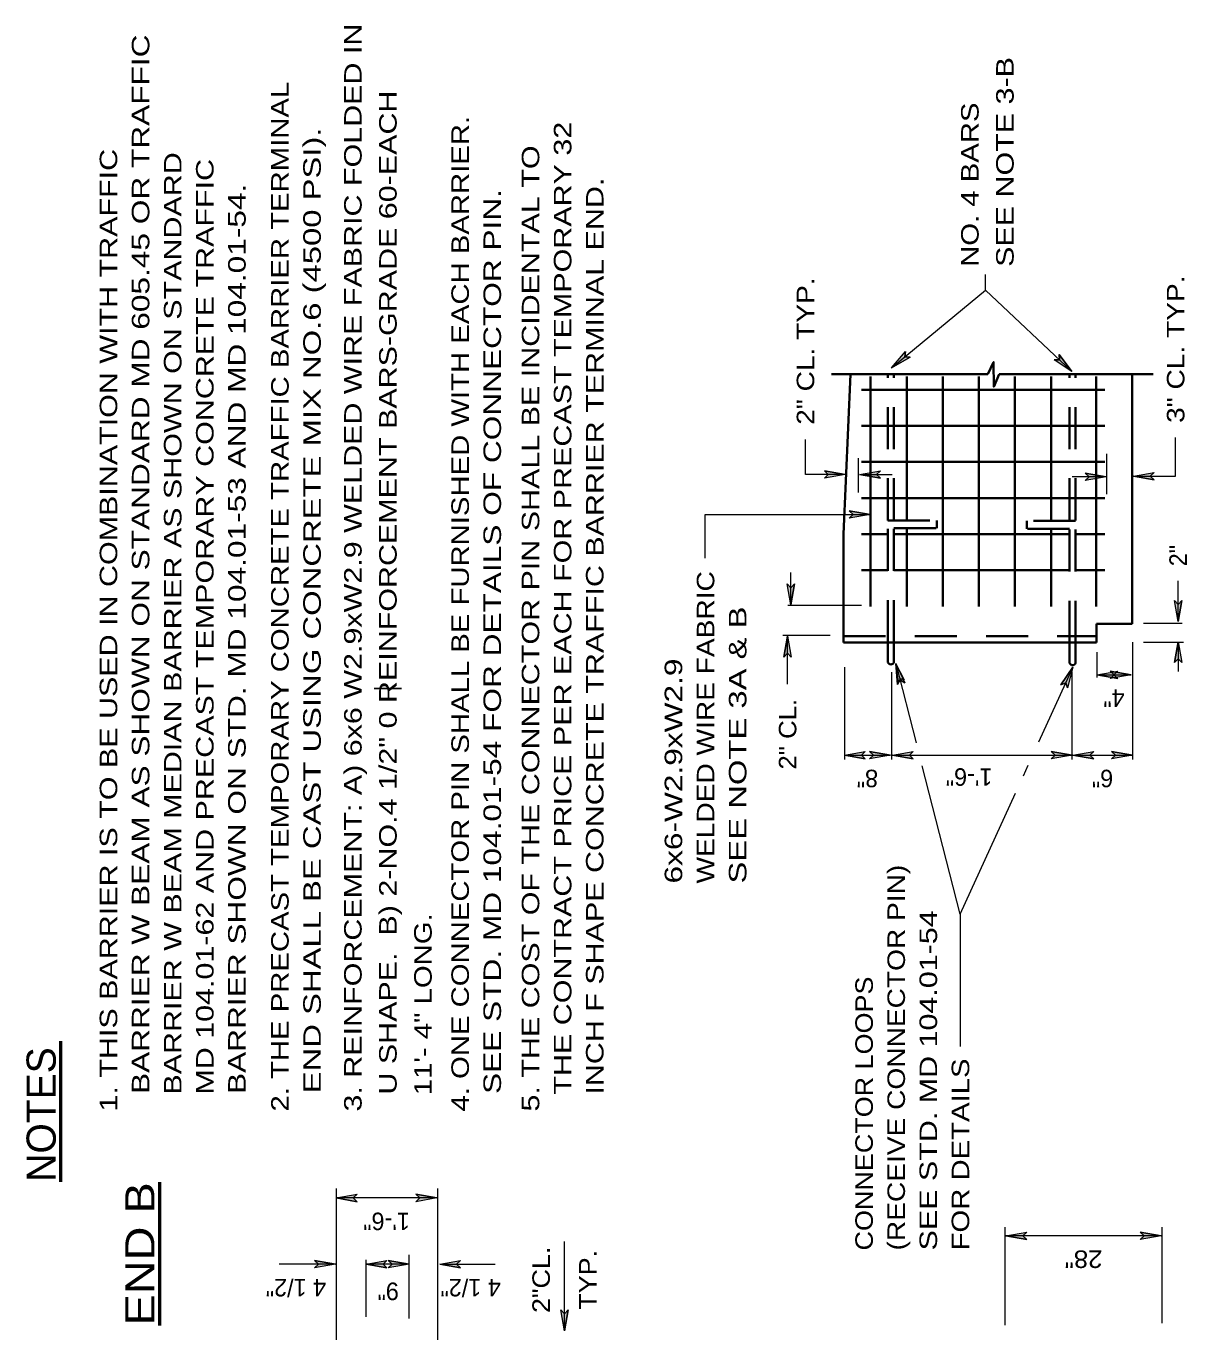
# Model space of a CAD drawing. Extents: x 12.6 to 19.4, y 6.1 to 16.3.
# Drawn here: x 12.609 to 16.585, y 11.844 to 16.317 of the extents above; entities that cross this region are included whole.
import ezdxf
from ezdxf.enums import TextEntityAlignment as Align

# ---------------------------------------------------------------- set-up
doc = ezdxf.new("R2010")
doc.units = 0
doc.header["$LTSCALE"] = 0.024
doc.linetypes.add('LONG_DASHED', pattern=[7.5, 6, -1.5])
for name, color, linetype, lineweight in [('1', 7, 'Continuous', 35), ('10', 7, 'Continuous', 13), ('12', 7, 'Continuous', 53), ('13', 7, 'Continuous', 53)]:
    doc.layers.add(name, color=color, linetype=linetype, lineweight=lineweight)

msp = doc.modelspace()

# ---------------------------------------------------------------- hatches: boundary and pattern name
at = {"layer": '10'}
for points in [[(15.6367, 15.1824), (15.5735, 15.1466), (15.6206, 15.2018), (15.6182, 15.1835)], [(16.1475, 15.1916), (16.1909, 15.1334), (16.1302, 15.1733), (16.1487, 15.1732)], [(15.3432, 14.7935), (15.4147, 14.7809), (15.3432, 14.7683), (15.3567, 14.7809)], [(15.5351, 14.7683), (15.4636, 14.7809), (15.5351, 14.7935), (15.5216, 14.7809)], [(16.2369, 14.7857), (16.3084, 14.7731), (16.2369, 14.7605), (16.2504, 14.7731)], [(16.4731, 14.7626), (16.4016, 14.7752), (16.4731, 14.7878), (16.4596, 14.7752)], [(15.4286, 14.6562), (15.5001, 14.6436), (15.4286, 14.631), (15.4421, 14.6436)], [(15.2411, 14.4059), (15.2285, 14.3344), (15.2159, 14.4059), (15.2285, 14.3924)], [(16.5675, 14.3487), (16.5549, 14.2772), (16.5423, 14.3487), (16.5549, 14.3352)], [(15.2046, 14.1552), (15.2172, 14.2267), (15.2298, 14.1552), (15.2172, 14.1687)], [(16.5423, 14.1362), (16.5549, 14.2077), (16.5675, 14.1362), (16.5549, 14.1497)], [(15.5938, 14.0612), (15.5883, 14.1336), (15.6182, 14.0675), (15.6027, 14.0774)], [(16.1528, 14.0604), (16.1939, 14.1202), (16.1757, 14.0499), (16.1698, 14.0674)], [(16.3484, 14.0821), (16.2769, 14.0947), (16.3484, 14.1073), (16.3349, 14.0947)], [(16.3224, 14.1073), (16.3939, 14.0947), (16.3224, 14.0821), (16.3359, 14.0947)], [(15.4833, 13.8069), (15.4118, 13.8195), (15.4833, 13.8321), (15.4698, 13.8195)], [(15.4979, 13.8321), (15.5694, 13.8195), (15.4979, 13.8069), (15.5114, 13.8195)], [(15.6478, 13.8069), (15.5763, 13.8195), (15.6478, 13.8321), (15.6343, 13.8195)], [(16.1204, 13.8321), (16.1919, 13.8195), (16.1204, 13.8069), (16.1339, 13.8195)], [(16.2656, 13.8069), (16.1941, 13.8195), (16.2656, 13.8321), (16.2521, 13.8195)], [(16.3266, 13.8321), (16.3981, 13.8195), (16.3266, 13.8069), (16.3401, 13.8195)], [(13.7428, 12.2898), (13.6713, 12.3024), (13.7428, 12.315), (13.7293, 12.3024)], [(13.944, 12.315), (14.0155, 12.3024), (13.944, 12.2898), (13.9575, 12.3024)], [(16.0367, 12.1602), (15.9652, 12.1728), (16.0367, 12.1854), (16.0232, 12.1728)], [(16.4252, 12.1854), (16.4967, 12.1728), (16.4252, 12.1602), (16.4387, 12.1728)], [(13.5966, 12.088), (13.6681, 12.0754), (13.5966, 12.0628), (13.6101, 12.0754)], [(13.8449, 12.0628), (13.7734, 12.0754), (13.8449, 12.088), (13.8314, 12.0754)], [(13.8491, 12.088), (13.9206, 12.0754), (13.8491, 12.0628), (13.8626, 12.0754)], [(14.0969, 12.0628), (14.0254, 12.0754), (14.0969, 12.088), (14.0834, 12.0754)], [(14.4655, 11.9189), (14.4529, 11.8474), (14.4403, 11.9189), (14.4529, 11.9054)]]:
    msp.add_hatch(color=256, dxfattribs=at).paths.add_polyline_path(points)

# ---------------------------------------------------------------- linework, layer by layer
at = {"layer": '1'}
for p, q in [((15.3677, 15.1243), (15.9034, 15.1243)), ((16.4689, 15.1243), (15.9421, 15.1243)), ((16.3978, 14.2686), (16.3978, 15.1243)), ((15.5014, 15.1161), (15.5014, 14.3284)), ((15.6251, 15.1161), (15.6251, 14.6236)), ((15.7487, 15.1161), (15.7487, 14.3284)), ((15.8723, 15.1161), (15.8723, 14.3284)), ((15.9959, 15.1161), (15.9959, 14.3284)), ((16.1195, 15.1161), (16.1195, 14.6215)), ((16.2742, 14.3284), (16.2742, 15.1161)), ((15.4706, 15.0709), (16.3039, 15.0709)), ((15.4706, 14.9473), (16.3039, 14.9473)), ((15.4706, 14.8237), (16.3039, 14.8237)), ((15.4706, 14.7), (16.3039, 14.7)), ((15.6251, 14.3284), (15.6251, 14.5969)), ((16.1195, 14.3284), (16.1195, 14.5948)), ((15.4706, 14.5765), (15.5607, 14.5765)), ((16.1828, 14.5765), (15.5816, 14.5765)), ((16.3039, 14.5765), (16.2037, 14.5765)), ((15.4706, 14.4527), (15.5607, 14.4527)), ((16.1828, 14.4527), (15.5816, 14.4527)), ((16.3039, 14.4527), (16.2037, 14.4527)), ((16.275, 14.2686), (16.3978, 14.2686)), ((16.275, 14.2056), (16.275, 14.2686)), ((16.275, 14.2056), (15.4087, 14.2056)), ((15.5607, 14.2064), (15.5607, 14.137)), ((15.5816, 14.2064), (15.5816, 14.137)), ((16.1828, 14.2042), (16.1828, 14.1349)), ((16.2037, 14.2042), (16.2037, 14.1349))]:
    msp.add_line(p, q, dxfattribs=at)
at = {"layer": '1', "linetype": 'LONG_DASHED'}
for p, q in [((15.5607, 14.6236), (15.5607, 15.1243)), ((15.5816, 14.6236), (15.5816, 15.1243)), ((16.1828, 14.6236), (16.1828, 15.1243)), ((16.2037, 14.6236), (16.2037, 15.1243)), ((15.5607, 14.2064), (15.5607, 14.6236)), ((15.5607, 14.6236), (15.728, 14.6236)), ((15.728, 14.5969), (15.728, 14.6236)), ((16.2037, 14.6215), (16.0364, 14.6215)), ((16.0364, 14.5948), (16.0364, 14.6215)), ((16.2037, 14.2042), (16.2037, 14.6215)), ((15.4088, 14.2268), (16.275, 14.2268))]:
    msp.add_line(p, q, dxfattribs=at)
at = {"layer": '1'}
msp.add_lwpolyline([(15.4087, 14.2056), (15.4087, 14.5765), (15.4331, 15.1243)], dxfattribs=at)
at = {"layer": '1', "linetype": 'LONG_DASHED'}
for points in [[(15.5816, 14.2064), (15.5816, 14.5969), (15.728, 14.5969)], [(16.1828, 14.2042), (16.1828, 14.5948), (16.0364, 14.5948)]]:
    msp.add_lwpolyline(points, dxfattribs=at)
at = {"layer": '1'}
for centre, radius, start, end in [((15.5712, 14.1414), 0.0113, 202.6097, 337.3903), ((16.1934, 14.1385), 0.0111, 199.1845, 340.8155)]:
    msp.add_arc(centre, radius, start, end, dxfattribs=at)
at = {"layer": '10'}
for p, q in [((15.8954, 15.4121), (16.1909, 15.1334)), ((15.5735, 15.1466), (15.6206, 15.2018)), ((15.5735, 15.1466), (15.6367, 15.1824)), ((16.1909, 15.1334), (16.1302, 15.1733)), ((16.1909, 15.1334), (16.1475, 15.1916)), ((15.2784, 14.7809), (15.2784, 14.9009)), ((16.5464, 14.7752), (16.5464, 14.9073)), ((16.3108, 14.7133), (16.3108, 14.8515)), ((15.4605, 14.7195), (15.4605, 14.8362)), ((15.4147, 14.7809), (15.2784, 14.7809)), ((15.4147, 14.7809), (15.3432, 14.7935)), ((15.4147, 14.7809), (15.3432, 14.7683)), ((15.4636, 14.7809), (15.5351, 14.7935)), ((15.4636, 14.7809), (15.5758, 14.7809)), ((15.4636, 14.7809), (15.5351, 14.7683)), ((16.3084, 14.7731), (16.1923, 14.7731)), ((16.3084, 14.7731), (16.2369, 14.7857)), ((16.3084, 14.7731), (16.2369, 14.7605)), ((16.4016, 14.7752), (16.4731, 14.7878)), ((16.4016, 14.7752), (16.5464, 14.7752)), ((16.4016, 14.7752), (16.4731, 14.7626)), ((15.5001, 14.6436), (15.4286, 14.6562)), ((15.5001, 14.6436), (15.4286, 14.631)), ((15.2285, 14.3344), (15.2159, 14.4059)), ((15.2285, 14.3344), (15.2285, 14.445)), ((15.2285, 14.3344), (15.2411, 14.4059)), ((16.5549, 14.2772), (16.5549, 14.4163)), ((15.4705, 14.3314), (15.2184, 14.3314)), ((16.5549, 14.2772), (16.5423, 14.3487)), ((16.5549, 14.2772), (16.5675, 14.3487)), ((16.4362, 14.2717), (16.5688, 14.2717)), ((15.3632, 14.2297), (15.2006, 14.2297)), ((15.2172, 14.2267), (15.2046, 14.1552)), ((15.2172, 14.0623), (15.2172, 14.2267)), ((15.2172, 14.2267), (15.2298, 14.1552)), ((16.3982, 14.2064), (16.3982, 13.8049)), ((16.4362, 14.2069), (16.5729, 14.2069)), ((16.5549, 14.2077), (16.5423, 14.1362)), ((16.5549, 14.2077), (16.5549, 14.1063)), ((16.5549, 14.2077), (16.5675, 14.1362)), ((16.2769, 14.1718), (16.2769, 14.0857)), ((15.4118, 14.1208), (15.4118, 13.8049)), ((15.5734, 14.1034), (15.5734, 13.8049)), ((15.5972, 14.0704), (15.5883, 14.1336)), ((15.6172, 14.0767), (15.5883, 14.1336)), ((15.5883, 14.1336), (15.658, 13.8615)), ((15.5883, 14.1336), (15.5938, 14.0612)), ((15.5883, 14.1336), (15.6182, 14.0675)), ((16.1939, 14.1202), (16.0771, 13.8639)), ((16.1939, 14.1202), (16.1528, 14.0604)), ((16.1939, 14.1202), (16.1757, 14.0499)), ((16.1912, 14.1034), (16.1912, 13.8049)), ((16.2769, 14.0947), (16.3484, 14.1073)), ((16.2769, 14.0947), (16.3939, 14.0947)), ((16.2769, 14.0947), (16.3484, 14.0821)), ((16.3939, 14.0947), (16.3224, 14.1073)), ((16.3939, 14.0947), (16.3224, 14.0821)), ((15.5972, 14.0704), (15.6049, 14.081)), ((15.6172, 14.0767), (15.6049, 14.081)), ((15.4118, 13.8195), (15.4833, 13.8321)), ((15.5694, 13.8195), (15.4979, 13.8321)), ((15.5763, 13.8195), (15.6478, 13.8321)), ((16.1919, 13.8195), (16.1204, 13.8321)), ((16.1941, 13.8195), (16.2656, 13.8321)), ((16.3981, 13.8195), (16.3266, 13.8321)), ((15.4118, 13.8195), (15.5694, 13.8195)), ((15.4118, 13.8195), (15.4833, 13.8069)), ((15.5694, 13.8195), (15.4979, 13.8069)), ((15.5763, 13.8195), (16.1919, 13.8195)), ((15.5763, 13.8195), (15.6478, 13.8069)), ((15.8083, 13.2743), (15.6783, 13.7823)), ((16.0248, 13.749), (16.0413, 13.7853)), ((16.1919, 13.8195), (16.1204, 13.8069)), ((16.1941, 13.8195), (16.3981, 13.8195)), ((16.1941, 13.8195), (16.2656, 13.8069)), ((16.3981, 13.8195), (16.3266, 13.8069)), ((15.8083, 13.2743), (15.9974, 13.689)), ((15.8092, 12.8209), (15.8092, 13.276)), ((13.6713, 12.3024), (13.7428, 12.315)), ((14.0155, 12.3024), (13.6713, 12.3024)), ((13.6713, 12.3024), (13.7428, 12.2898)), ((13.6715, 11.6327), (13.6715, 12.3353)), ((14.0155, 12.3024), (13.944, 12.315)), ((14.0155, 12.3024), (13.944, 12.2898)), ((14.0189, 11.659), (14.0189, 12.3353)), ((15.9625, 11.8669), (15.9625, 12.2024)), ((15.9652, 12.1728), (16.0367, 12.1854)), ((16.4967, 12.1728), (15.9652, 12.1728)), ((15.9652, 12.1728), (16.0367, 12.1602)), ((16.4967, 12.1728), (16.4252, 12.1854)), ((16.4967, 12.1728), (16.4252, 12.1602)), ((16.5, 11.8734), (16.5, 12.2024)), ((14.4529, 11.8474), (14.4529, 12.1533)), ((13.6681, 12.0754), (13.5966, 12.088)), ((13.7734, 11.8959), (13.7734, 12.0907)), ((13.7734, 12.0754), (13.8449, 12.088)), ((13.9206, 12.0754), (13.8491, 12.088)), ((13.9206, 11.8893), (13.9206, 12.1073)), ((14.0254, 12.0754), (14.0969, 12.088)), ((13.6681, 12.0754), (13.476, 12.0754)), ((13.6681, 12.0754), (13.5966, 12.0628)), ((13.9206, 12.0754), (13.7734, 12.0754)), ((13.7734, 12.0754), (13.8449, 12.0628)), ((13.9206, 12.0754), (13.8491, 12.0628)), ((14.0254, 12.0754), (14.2156, 12.0754)), ((14.0254, 12.0754), (14.0969, 12.0628)), ((14.4529, 11.8474), (14.4403, 11.9189)), ((14.4529, 11.8474), (14.4655, 11.9189))]:
    msp.add_line(p, q, dxfattribs=at)
for points in [[(15.5735, 15.1466), (15.8954, 15.4121), (15.8954, 15.4658)], [(15.6367, 15.1824), (15.6182, 15.1835), (15.6206, 15.2018)], [(16.1475, 15.1916), (16.1487, 15.1732), (16.1302, 15.1733)], [(15.3432, 14.7935), (15.3567, 14.7809), (15.3432, 14.7683)], [(15.5351, 14.7683), (15.5216, 14.7809), (15.5351, 14.7935)], [(16.2369, 14.7857), (16.2504, 14.7731), (16.2369, 14.7605)], [(16.4731, 14.7626), (16.4596, 14.7752), (16.4731, 14.7878)], [(14.9349, 14.494), (14.9349, 14.6436), (15.5001, 14.6436)], [(15.4286, 14.6562), (15.4421, 14.6436), (15.4286, 14.631)], [(15.2411, 14.4059), (15.2285, 14.3924), (15.2159, 14.4059)], [(16.5675, 14.3487), (16.5549, 14.3352), (16.5423, 14.3487)], [(15.2046, 14.1552), (15.2172, 14.1687), (15.2298, 14.1552)], [(16.5423, 14.1362), (16.5549, 14.1497), (16.5675, 14.1362)], [(16.3224, 14.1073), (16.3359, 14.0947), (16.3224, 14.0821)], [(16.3484, 14.0821), (16.3349, 14.0947), (16.3484, 14.1073)], [(15.5938, 14.0612), (15.6027, 14.0774), (15.6182, 14.0675)], [(16.1528, 14.0604), (16.1698, 14.0674), (16.1757, 14.0499)], [(15.4833, 13.8069), (15.4698, 13.8195), (15.4833, 13.8321)], [(15.4979, 13.8321), (15.5114, 13.8195), (15.4979, 13.8069)], [(15.6478, 13.8069), (15.6343, 13.8195), (15.6478, 13.8321)], [(16.1204, 13.8321), (16.1339, 13.8195), (16.1204, 13.8069)], [(16.2656, 13.8069), (16.2521, 13.8195), (16.2656, 13.8321)], [(16.3266, 13.8321), (16.3401, 13.8195), (16.3266, 13.8069)], [(13.7428, 12.2898), (13.7293, 12.3024), (13.7428, 12.315)], [(13.944, 12.315), (13.9575, 12.3024), (13.944, 12.2898)], [(16.0367, 12.1602), (16.0232, 12.1728), (16.0367, 12.1854)], [(16.4252, 12.1854), (16.4387, 12.1728), (16.4252, 12.1602)], [(13.5966, 12.088), (13.6101, 12.0754), (13.5966, 12.0628)], [(13.8449, 12.0628), (13.8314, 12.0754), (13.8449, 12.088)], [(13.8491, 12.088), (13.8626, 12.0754), (13.8491, 12.0628)], [(14.0969, 12.0628), (14.0834, 12.0754), (14.0969, 12.088)], [(14.4655, 11.9189), (14.4529, 11.9054), (14.4403, 11.9189)]]:
    msp.add_lwpolyline(points, dxfattribs=at)
for points in [[(15.6367, 15.1824), (15.5735, 15.1466), (15.6206, 15.2018), (15.6182, 15.1835)], [(16.1475, 15.1916), (16.1909, 15.1334), (16.1302, 15.1733), (16.1487, 15.1732)], [(15.3432, 14.7935), (15.4147, 14.7809), (15.3432, 14.7683), (15.3567, 14.7809)], [(15.5351, 14.7683), (15.4636, 14.7809), (15.5351, 14.7935), (15.5216, 14.7809)], [(16.2369, 14.7857), (16.3084, 14.7731), (16.2369, 14.7605), (16.2504, 14.7731)], [(16.4731, 14.7626), (16.4016, 14.7752), (16.4731, 14.7878), (16.4596, 14.7752)], [(15.4286, 14.6562), (15.5001, 14.6436), (15.4286, 14.631), (15.4421, 14.6436)], [(15.2411, 14.4059), (15.2285, 14.3344), (15.2159, 14.4059), (15.2285, 14.3924)], [(16.5675, 14.3487), (16.5549, 14.2772), (16.5423, 14.3487), (16.5549, 14.3352)], [(15.2046, 14.1552), (15.2172, 14.2267), (15.2298, 14.1552), (15.2172, 14.1687)], [(16.5423, 14.1362), (16.5549, 14.2077), (16.5675, 14.1362), (16.5549, 14.1497)], [(15.5938, 14.0612), (15.5883, 14.1336), (15.6182, 14.0675), (15.6027, 14.0774)], [(16.1528, 14.0604), (16.1939, 14.1202), (16.1757, 14.0499), (16.1698, 14.0674)], [(16.3484, 14.0821), (16.2769, 14.0947), (16.3484, 14.1073), (16.3349, 14.0947)], [(16.3224, 14.1073), (16.3939, 14.0947), (16.3224, 14.0821), (16.3359, 14.0947)], [(15.4833, 13.8069), (15.4118, 13.8195), (15.4833, 13.8321), (15.4698, 13.8195)], [(15.4979, 13.8321), (15.5694, 13.8195), (15.4979, 13.8069), (15.5114, 13.8195)], [(15.6478, 13.8069), (15.5763, 13.8195), (15.6478, 13.8321), (15.6343, 13.8195)], [(16.1204, 13.8321), (16.1919, 13.8195), (16.1204, 13.8069), (16.1339, 13.8195)], [(16.2656, 13.8069), (16.1941, 13.8195), (16.2656, 13.8321), (16.2521, 13.8195)], [(16.3266, 13.8321), (16.3981, 13.8195), (16.3266, 13.8069), (16.3401, 13.8195)], [(13.7428, 12.2898), (13.6713, 12.3024), (13.7428, 12.315), (13.7293, 12.3024)], [(13.944, 12.315), (14.0155, 12.3024), (13.944, 12.2898), (13.9575, 12.3024)], [(16.0367, 12.1602), (15.9652, 12.1728), (16.0367, 12.1854), (16.0232, 12.1728)], [(16.4252, 12.1854), (16.4967, 12.1728), (16.4252, 12.1602), (16.4387, 12.1728)], [(13.5966, 12.088), (13.6681, 12.0754), (13.5966, 12.0628), (13.6101, 12.0754)], [(13.8449, 12.0628), (13.7734, 12.0754), (13.8449, 12.088), (13.8314, 12.0754)], [(13.8491, 12.088), (13.9206, 12.0754), (13.8491, 12.0628), (13.8626, 12.0754)], [(14.0969, 12.0628), (14.0254, 12.0754), (14.0969, 12.088), (14.0834, 12.0754)], [(14.4655, 11.9189), (14.4529, 11.8474), (14.4403, 11.9189), (14.4529, 11.9054)]]:
    msp.add_lwpolyline(points, close=True, dxfattribs=at)
at = {"layer": '10', "lineweight": 35}
msp.add_lwpolyline([(15.9423, 15.1245), (15.9232, 15.081), (15.9226, 15.1659), (15.9029, 15.1245)], dxfattribs=at)
at = {"layer": '12'}
msp.add_line((13.0672, 11.8655), (13.0672, 12.3565), dxfattribs=at)
at = {"layer": '13', "lineweight": 25}
msp.add_line((13.8008, 14.0475), (13.8941, 14.0475), dxfattribs=at)
at = {"layer": '13'}
msp.add_line((12.7274, 12.358), (12.7274, 12.8392), dxfattribs=at)

# ---------------------------------------------------------------- texts
at = {"layer": '12'}
for s, width, p in [('SEE NOTE 3-B', 1.3, (15.9916, 15.4919)), ('NO. 4 BARS', 1.25, (15.8716, 15.4919)), ('2" CL. TYP.', 1.2, (15.3084, 14.9509)), ('3" CL. TYP.', 1.2, (16.5764, 14.9573)), ('WELDED WIRE FABRIC', 1.2, (14.9661, 13.3797)), ('SEE NOTE 3A & B', 1.4, (15.0761, 13.3796)), ('6x6-W2.9xW2.9', 1.35, (14.8561, 13.3797)), ('(RECEIVE CONNECTOR PIN)', 1.2, (15.6192, 12.1227)), ('SEE STD. MD 104.01-54', 1.3, (15.7292, 12.1227)), ('CONNECTOR LOOPS', 1.15, (15.5092, 12.1227)), ('FOR DETAILS', 1.25, (15.8392, 12.1227))]:
    msp.add_text(s, height=0.06, rotation=90, dxfattribs=dict(at, width=width)).set_placement(p)
msp.add_text('2"', height=0.06, rotation=90, dxfattribs=at).set_placement((16.5849, 14.4663))
for s, p in [('4"', (16.3353, 14.0446)), ('8"', (15.4906, 13.7694)), ('1\'-6"', (15.8389, 13.7744)), ('6"', (16.296, 13.7694)), ('1\'-6"', (13.8434, 12.2523)), ('4 1/2" ', (13.522, 12.0254)), ('9"', (13.8491, 12.0127)), ('4 1/2" ', (14.1204, 12.0254))]:
    msp.add_text(s, height=0.06, rotation=180, dxfattribs=at).set_placement(p, align=Align.CENTER)
at = {"layer": '12', "width": 1.1}
msp.add_text('2" CL.', height=0.06, rotation=90, dxfattribs=at).set_placement((15.2472, 14.0123), align=Align.RIGHT)
at = {"layer": '12'}
for s, height, rotation, width, p in [('END B', 0.1, 90, 1.2, (13.0484, 12.111)), ('2"CL.', 0.06, 90, 1.15, (14.4029, 12.0221)), ('28"', 0.06, 180, 1.1, (16.231, 12.1227)), ('TYP.', 0.06, 90, 1.15, (14.5629, 12.0221))]:
    msp.add_text(s, height=height, rotation=rotation, dxfattribs=dict(at, width=width)).set_placement(p, align=Align.CENTER)
at = {"layer": '13'}
for s, width, p in [('  BARRIER W BEAM AS SHOWN ON STANDARD MD 605.45 OR TRAFFIC', 1.35, (13.0309, 12.5986)), ('3. REINFORCEMENT: A) 6x6 W2.9xW2.9 WELDED WIRE FABRIC FOLDED IN', 1.3, (13.7581, 12.5986)), ('2. THE PRECAST TEMPORARY CONCRETE TRAFFIC BARRIER TERMINAL', 1.25, (13.5082, 12.5986)), ('  U SHAPE.  B) 2-NO.4 1/2" 0 REINFORCEMENT BARS-GRADE 60-EACH', 1.3, (13.8781, 12.5986)), ('4. ONE CONNECTOR PIN SHALL BE FURNISHED WITH EACH BARRIER.', 1.25, (14.1255, 12.5986)), ('  THE CONTRACT PRICE PER EACH FOR PRECAST TEMPORARY 32', 1.3, (14.4766, 12.5986)), ('  END SHALL BE CAST USING CONCRETE MIX NO.6 (4500 PSI).', 1.4, (13.6182, 12.5986)), ('1. THIS BARRIER IS TO BE USED IN COMBINATION WITH TRAFFIC', 1.3, (12.9209, 12.5986)), ('  BARRIER W BEAM MEDIAN BARRIER AS SHOWN ON STANDARD', 1.3, (13.1409, 12.5986)), ('5. THE COST OF THE CONNECTOR PIN SHALL BE INCIDENTAL TO', 1.3, (14.3666, 12.5986)), ('  MD 104.01-62 AND PRECAST TEMPORARY CONCRETE TRAFFIC', 1.3, (13.2509, 12.5986)), ('  BARRIER SHOWN ON STD. MD 104.01-53 AND MD 104.01-54.', 1.35, (13.3609, 12.5986)), ('  SEE STD. MD 104.01-54 FOR DETAILS OF CONNECTOR PIN.', 1.35, (14.2355, 12.5986)), ('  INCH F SHAPE CONCRETE TRAFFIC BARRIER TERMINAL END.', 1.3, (14.5866, 12.5986)), ('  11\'- 4" LONG.', 1.25, (13.9981, 12.5986))]:
    msp.add_text(s, height=0.06, rotation=90, dxfattribs=dict(at, width=width)).set_placement(p)
msp.add_text('NOTES', height=0.1, rotation=90, dxfattribs=at).set_placement((12.7103, 12.358))

doc.saveas('drawing.dxf')
